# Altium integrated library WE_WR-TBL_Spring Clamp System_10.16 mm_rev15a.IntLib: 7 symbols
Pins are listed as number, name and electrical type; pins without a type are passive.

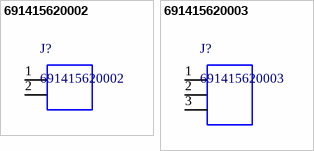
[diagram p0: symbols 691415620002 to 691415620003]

## 691415620002
designator J?
WR-TBL 45° Cable Entry Screwless, Serie 4156 - 10.16 mm; Manufacturer: Wurth Elektronik; ComponentLink1 Description: Manufacturer; ComponentLink2 Description: Datasheet
footprint 691415620002 (Serie 4156 - 10.16 mm _ 2 pins)
pins: 1, 2

## 691415620003
designator J?
WR-TBL 45° Cable Entry Screwless, Serie 4156 - 10.16 mm; Manufacturer: Wurth Elektronik; ComponentLink1 Description: Manufacturer; ComponentLink2 Description: Datasheet
footprint 691415620003 (Serie 4156 - 10.16 mm _ 3 pins)
pins: 1, 2, 3


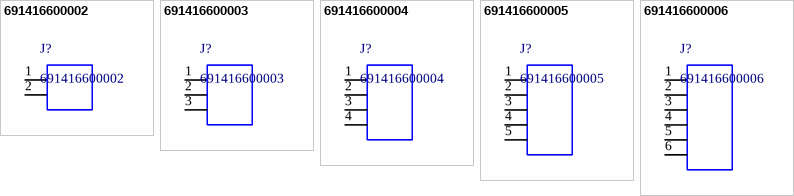
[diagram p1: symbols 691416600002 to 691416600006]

## 691416600002
designator J?
WR-TBL Vertical Cable Entry Screwless, Serie 4166 - 10.16 mm; Manufacturer: Wurth Elektronik; ComponentLink1 Description: Manufacturer; ComponentLink2 Description: Datasheet
footprint 691416600002 (Serie 4166 - 10.16 mm _ 2 pins)
pins: 1, 2

## 691416600003
designator J?
WR-TBL Vertical Cable Entry Screwless, Serie 4166 - 10.16 mm; Manufacturer: Wurth Elektronik; ComponentLink1 Description: Manufacturer; ComponentLink2 Description: Datasheet
footprint 691416600003 (Serie 4166 - 10.16 mm _ 3 pins)
pins: 1, 2, 3

## 691416600004
designator J?
WR-TBL Vertical Cable Entry Screwless, Serie 4166 - 10.16 mm; Manufacturer: Wurth Elektronik; ComponentLink1 Description: Manufacturer; ComponentLink2 Description: Datasheet
footprint 691416600004 (Serie 4166 - 10.16 mm _ 4 pins)
pins: 1, 2, 3, 4

## 691416600005
designator J?
WR-TBL Vertical Cable Entry Screwless, Serie 4166 - 10.16 mm; Manufacturer: Wurth Elektronik; ComponentLink1 Description: Manufacturer; ComponentLink2 Description: Datasheet
footprint 691416600005 (Serie 4166 - 10.16 mm _ 5 pins)
pins: 1, 2, 3, 4, 5

## 691416600006
designator J?
WR-TBL Vertical Cable Entry Screwless, Serie 4166 - 10.16 mm; Manufacturer: Wurth Elektronik; ComponentLink1 Description: Manufacturer; ComponentLink2 Description: Datasheet
footprint 691416600006 (Serie 4166 - 10.16 mm _ 6 pins)
pins: 1, 2, 3, 4, 5, 6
